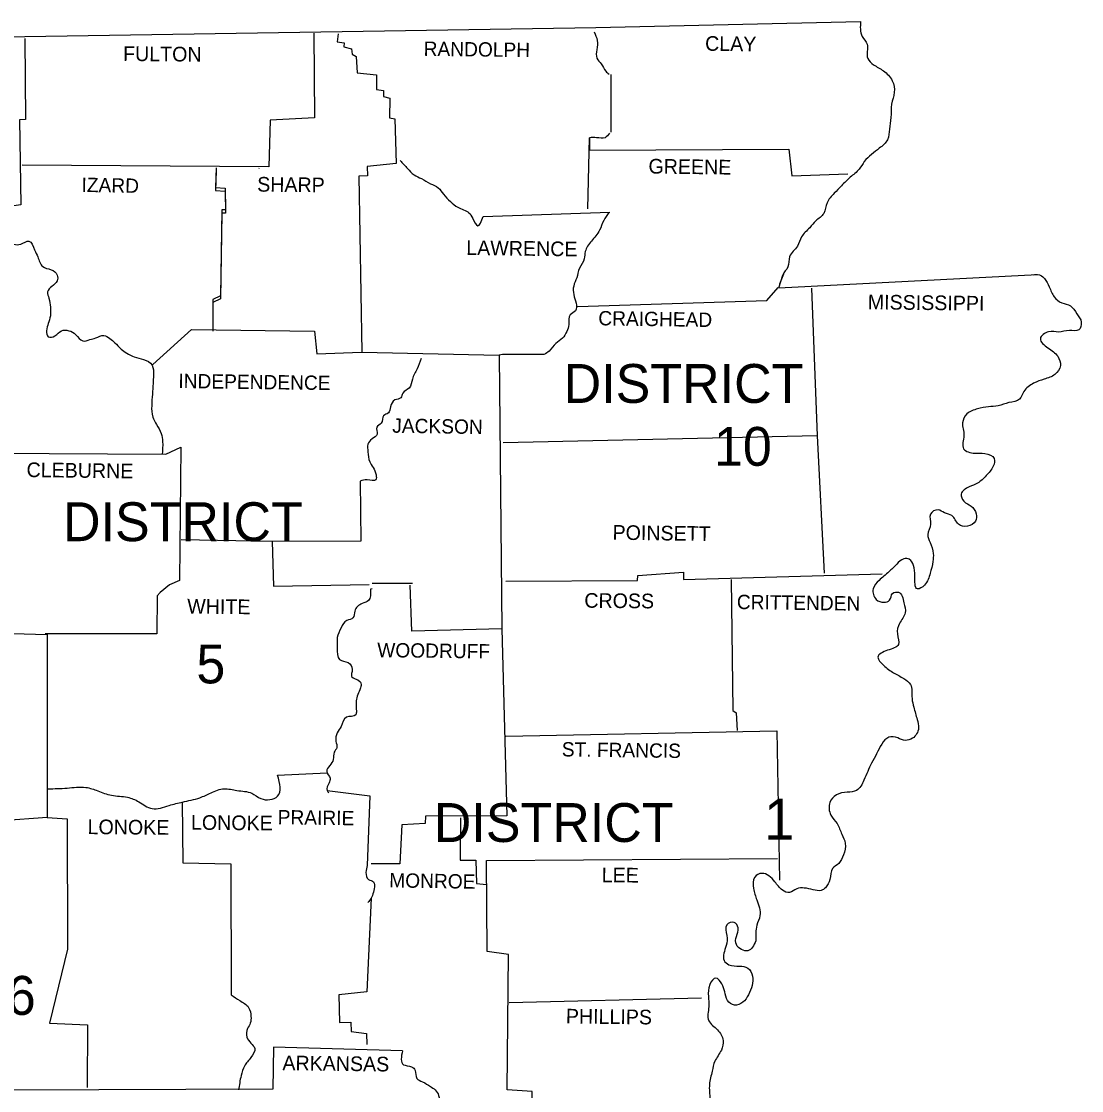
# Model space of a CAD drawing. Extents: x -17668 to 16999, y -17303 to 5867.
# Drawn here: x -16002 to -14292, y 4141 to 5867 of the extents above; entities that cross this region are included whole.
import ezdxf

# ---------------------------------------------------------------- set-up
doc = ezdxf.new("R2010")
doc.units = 0
for name, color, linetype in [('1', 7, 'Continuous'), ('2', 7, 'Continuous'), ('3', 7, 'Continuous')]:
    doc.layers.add(name, color=color, linetype=linetype)

msp = doc.modelspace()

# ---------------------------------------------------------------- linework, layer by layer
at = {"layer": '1'}
for p, q in [((-14780.6, 5436.9), (-14774, 5457.3)), ((-14779, 5443.5), (-14772.4, 5459.5)), ((-15436.7, 4960.3), (-15371.2, 4960.3))]:
    msp.add_line(p, q, dxfattribs=at)
for points in [[(-17667.8, 5841.4), (-16777.9, 5840.9), (-15996.9, 5842.5), (-15075.6, 5856.8), (-14648.6, 5866.7)], [(-15996.9, 5839.2), (-15995.8, 5708.2), (-16005.2, 5707.7), (-16003.5, 5570.7), (-16042.1, 5565.2), (-16038.8, 5528.3), (-16025.5, 5511.2), (-16026.6, 5467.7), (-16101.5, 5465), (-16104.2, 5397.8), (-16172.5, 5395.6), (-16175.8, 5314.2), (-16171.9, 5307.6), (-16170.3, 5177.7), (-16052.5, 5170), (-16054.2, 4880), (-15960.6, 4877.2), (-15960.6, 4582.2), (-16034.4, 4576.7), (-16039.9, 4511.8), (-16163.7, 4511.2)], [(-15530.8, 5847.5), (-15529.7, 5711), (-15601.2, 5707.1), (-15603.4, 5632.3), (-16001.3, 5634.5)], [(-15491.2, 5846.9), (-15492.8, 5833.7), (-15481.8, 5832.1), (-15482.3, 5825.5), (-15469.7, 5822.7), (-15468.6, 5813.9), (-15462.5, 5810.1), (-15460.9, 5783.6), (-15429.5, 5780.3), (-15429.5, 5756.7), (-15418, 5755), (-15418, 5745.7), (-15408, 5742.9), (-15408.6, 5711), (-15399.8, 5709.3), (-15397.6, 5637.2), (-15444.4, 5632.8), (-15443.8, 5617.4), (-15458.1, 5616.9), (-15453.2, 5332.9), (-15231.4, 5327.9), (-15227.5, 4886.6), (-15372.3, 4882.7), (-15375, 4957)], [(-15051.4, 5780.9), (-15051.4, 5687.9)], [(-15088.8, 5564.1), (-15086.1, 5679.1), (-15086.1, 5658.7), (-14764.1, 5660.4), (-14759.7, 5617.4), (-14668.9, 5620.7)], [(-15688.2, 5630.6), (-15689.3, 5598.7), (-15673.9, 5597.6), (-15673.3, 5562.4), (-15678.8, 5562.4), (-15681, 5423.7), (-15693.7, 5418.2), (-15693.7, 5372)], [(-15688.2, 5625.7), (-15689.3, 5593.8), (-15673.9, 5592.7), (-15673.3, 5557.4), (-15678.8, 5557.4), (-15681, 5418.8), (-15693.7, 5413.3), (-15693.7, 5367)], [(-15619.4, 5629.5), (-15618.8, 5630.1)], [(-15257.3, 5551.9), (-15053.1, 5559.1)], [(-14780.6, 5436.9), (-14362.9, 5458.4)], [(-15105.4, 5406.7), (-14799.9, 5416.6), (-14781.7, 5437.5)], [(-14727.8, 5436.4), (-14718.5, 5198.1), (-14707.4, 4976.3)], [(-15790.5, 5313.1), (-15727.8, 5369.8), (-15529.7, 5367), (-15525.8, 5330.2), (-15453.7, 5332.9)], [(-15159.3, 5329.1), (-15226.4, 5329.1), (-15231.4, 5327.9)], [(-14718.5, 5198.1), (-15225.3, 5186.5)], [(-16052.5, 5170), (-15769.6, 5168.3), (-15745.4, 5179.9), (-15747.1, 4964.7), (-15763.6, 4957.6), (-15778.4, 4944.9), (-15783.4, 4940), (-15783.9, 4878.3), (-15963.9, 4878.3)], [(-15455.9, 5124.9), (-15454.8, 5028), (-15597.9, 5027.5), (-15744.9, 5030.2)], [(-15597.9, 5027.5), (-15595.7, 4955.4), (-15441.1, 4958.1)], [(-15220.9, 4963.6), (-15008.5, 4964.7), (-15007.9, 4972.4), (-14934.2, 4977.9), (-14934.2, 4966.4), (-14613.9, 4975.2)], [(-14857.1, 4966.4), (-14854.4, 4754.5), (-14849.4, 4751.2), (-14847.8, 4722.6)], [(-15436.7, 4951), (-15439.4, 4950.4)], [(-15227.5, 4886.6), (-15219.3, 4585), (-15350.3, 4584.4), (-15350.8, 4572.3), (-15388.8, 4570.1), (-15392.1, 4507.4), (-15438.3, 4507.4)], [(-15220.9, 4713.2), (-14783.9, 4722)], [(-14783.9, 4722), (-14779.5, 4481)], [(-15589.1, 4650.5), (-15509.3, 4654.3)], [(-15509.3, 4625.7), (-15440.5, 4616.9), (-15444.4, 4504.6)], [(-15743.2, 4607.5), (-15742.1, 4509), (-15664.5, 4507.4), (-15664, 4296)], [(-15960.6, 4582.2), (-15928.7, 4580), (-15928.1, 4369.8), (-15956.8, 4250.4), (-15895.7, 4247.6), (-15896.2, 4146.3)], [(-15294.1, 4581.7), (-15294.7, 4513.4), (-15269.4, 4513.4), (-15268.3, 4475.5), (-15252.3, 4473.8)], [(-15220.9, 4025.3), (-15178, 4028), (-15178.6, 4139.7), (-15218.7, 4142.5), (-15216.5, 4361), (-15251.2, 4365.9), (-15252.3, 4512.9), (-14782.8, 4516.2)], [(-15438.3, 4451.8), (-15444.9, 4301), (-15490.1, 4296), (-15489, 4251.5), (-15470.8, 4252), (-15470.2, 4236.6), (-15445.5, 4233.8), (-15444.9, 4215.7)], [(-15215.4, 4283.4), (-14905, 4291.1)], [(-15387.7, 4205.8), (-15595.7, 4211.3), (-15596.8, 4143.6), (-16017.8, 4141.9)]]:
    msp.add_lwpolyline(points, dxfattribs=at)
for points in [[(-14648.6, 5866.7), (-14645.8, 5842.5), (-14638.1, 5829.9), (-14637, 5806.8), (-14627.6, 5796.9), (-14611.7, 5786.9), (-14597.4, 5771), (-14594.1, 5752.3), (-14598.5, 5733), (-14599.6, 5711.5), (-14601.8, 5692.8), (-14605.1, 5675.8), (-14618.3, 5662), (-14630.9, 5652.1), (-14642.5, 5640.6), (-14650.8, 5628.4), (-14665.1, 5615.2), (-14679.4, 5601.5), (-14690.9, 5589.4), (-14702.5, 5574), (-14708, 5556.9), (-14720.7, 5544.8), (-14730.6, 5533.8), (-14743.8, 5518.9), (-14750.4, 5504.1), (-14763, 5487), (-14765.8, 5470.5), (-14774, 5457.3), (-14774.6, 5455.1)], [(-15078.4, 5849.7), (-15073.4, 5835.9), (-15074, 5821.1), (-15074, 5807.3), (-15066.8, 5798), (-15059.7, 5786.4), (-15054.2, 5781.4)], [(-15053.6, 5686.2), (-15060.8, 5679.1), (-15074.5, 5679.1), (-15086.1, 5679.1)], [(-15391.5, 5642.2), (-15379.4, 5629.5), (-15369, 5619.1), (-15356.9, 5613), (-15342.6, 5604.8), (-15329.9, 5598.2), (-15321.6, 5587.7), (-15310.1, 5576.2), (-15298.5, 5566.8), (-15280.4, 5558), (-15274.3, 5548.6), (-15266.1, 5537.1), (-15257.3, 5551.9)], [(-15054.7, 5558.5), (-15063, 5545.3), (-15069.6, 5529.9), (-15082.8, 5512.3), (-15092.7, 5495.3), (-15094.3, 5483.7), (-15102.1, 5468.3), (-15106.5, 5452.9), (-15111.4, 5439.7), (-15111.4, 5425.9), (-15107.6, 5412.2), (-15108.7, 5399.5), (-15116.9, 5393.4), (-15119.1, 5377.5), (-15122.4, 5366.5), (-15129.6, 5355.5), (-15140, 5347.2), (-15151, 5334.6), (-15159.3, 5329.1)], [(-16025.5, 5511.2), (-16003.5, 5507.4), (-15990.3, 5512.3), (-15981, 5498), (-15976, 5487), (-15967.8, 5471), (-15954.6, 5466.1), (-15944.6, 5457.3), (-15944.6, 5447.9), (-15953.4, 5439.1), (-15960.1, 5430.3), (-15957.9, 5419.9), (-15955.7, 5405.5), (-15955.7, 5391.8), (-15959, 5379.1), (-15961.7, 5367.6), (-15959, 5357.7), (-15948.5, 5359.3), (-15937.5, 5367.6), (-15925.9, 5367.6), (-15914.9, 5361.5), (-15903.4, 5351.1), (-15891.8, 5353.3), (-15882.5, 5356), (-15869.2, 5359.9), (-15859.9, 5354.9), (-15851.6, 5348.3), (-15841.7, 5337.9), (-15832.4, 5331.3), (-15820.3, 5325.2), (-15805.4, 5321.3), (-15791.6, 5312), (-15789.4, 5296), (-15790, 5282.3), (-15791.1, 5265.2), (-15792.2, 5246.5), (-15790.5, 5228.3), (-15784.5, 5216.2), (-15776.8, 5201.9), (-15774.6, 5188.7), (-15775.1, 5167.8)], [(-14369, 5457.8), (-14362.9, 5458.4), (-14344.2, 5438.6), (-14336, 5422.1), (-14323.9, 5412.7), (-14310.1, 5407.8), (-14299.6, 5395.1), (-14292.5, 5381.3), (-14296.3, 5369.2), (-14311.7, 5368.1), (-14328.8, 5365.4), (-14345.3, 5365.9), (-14358.5, 5354.9), (-14346.4, 5340.1), (-14330.5, 5326.3), (-14326.1, 5311.4), (-14334.9, 5297.1), (-14352.5, 5289.4), (-14369.5, 5282.8), (-14384.9, 5269.6), (-14392.1, 5257), (-14409.2, 5251.5), (-14426.8, 5246.5), (-14442.2, 5244.8), (-14459.8, 5241.5), (-14476.9, 5233.3), (-14484, 5219), (-14481.8, 5198.6), (-14482.4, 5177.2), (-14464.2, 5170), (-14448.2, 5169.4), (-14432.8, 5161.2), (-14434.5, 5149.1), (-14446, 5133.7), (-14459.8, 5121.6), (-14473.5, 5115.5), (-14486.2, 5104), (-14481.8, 5092.4), (-14470.2, 5084.7), (-14462, 5072), (-14463.1, 5060.5), (-14476.3, 5052.2), (-14490.6, 5055.5), (-14501.1, 5069.3), (-14513.2, 5073.7), (-14523.6, 5078.6), (-14535.7, 5071.5), (-14535.7, 5055.5), (-14540.1, 5038.5), (-14536.3, 5025.8), (-14531.3, 5008.2), (-14531.9, 4995), (-14536.3, 4976.3), (-14545.6, 4957), (-14556.7, 4951), (-14561.1, 4971.9), (-14563.3, 4988.9), (-14569.9, 4998.8), (-14578.7, 4999.4), (-14590.2, 4991.1), (-14602.9, 4978.5), (-14618.8, 4964.7), (-14628.2, 4951), (-14623.2, 4933.9), (-14611.1, 4929.5), (-14601.8, 4932.8), (-14596.8, 4943.8), (-14587.5, 4945.5), (-14578.7, 4928.4)], [(-15357.4, 5323), (-15364, 5305.9), (-15371.7, 5289.4), (-15376.7, 5275.1), (-15387.1, 5266.9), (-15390.4, 5259.2), (-15399.8, 5255.9), (-15406.9, 5244.8), (-15410.3, 5234.9), (-15418, 5230.5), (-15421.8, 5218.4), (-15429, 5211.8), (-15428.4, 5200.8), (-15436.7, 5193.1), (-15443.3, 5184.3), (-15443.3, 5172.2), (-15440.5, 5156.2), (-15435, 5146.9), (-15430.1, 5134.8), (-15430.6, 5127.1), (-15444.4, 5127.1), (-15455.9, 5124.9)], [(-15439.4, 4950.4), (-15442.2, 4932.2), (-15452.6, 4927.3), (-15464.7, 4915.2), (-15467.5, 4904.2), (-15477.4, 4899.8), (-15486.7, 4888.2), (-15492.8, 4872.3), (-15492.8, 4855.7), (-15489, 4837), (-15475.2, 4832.1), (-15468.6, 4821.1), (-15469.7, 4809.5), (-15456.5, 4801.8), (-15454.3, 4795.2), (-15456.5, 4788.1), (-15462.5, 4767.7), (-15462, 4753.9), (-15463.1, 4747.9), (-15477.9, 4744), (-15486.7, 4729.2), (-15492.8, 4718.7), (-15495, 4704.9), (-15493.4, 4695), (-15497.8, 4687.3), (-15499.4, 4675.8), (-15504.9, 4665.9), (-15509.9, 4656.5), (-15504.4, 4645.5), (-15506, 4637.8), (-15509.3, 4625.7), (-15506.6, 4621.8)], [(-14578.7, 4928.4), (-14576.5, 4912.4), (-14585.8, 4895.4), (-14589.1, 4878.3), (-14587.5, 4861.2), (-14605.1, 4851.9), (-14620.5, 4840.9), (-14611.7, 4827.7), (-14595.2, 4815.6), (-14578.7, 4806.2), (-14568.2, 4796.9), (-14565.5, 4774.3), (-14562.7, 4760), (-14557.2, 4740.2), (-14555, 4726.4), (-14564.9, 4709.9), (-14576.5, 4706.6), (-14588.6, 4710.5), (-14602.9, 4711.6), (-14614.4, 4700.5), (-14622.7, 4685.1), (-14630.9, 4669.7), (-14637, 4656.5), (-14643.1, 4642.2), (-14655.2, 4625.7), (-14670, 4622.9), (-14687.6, 4618.5), (-14698.1, 4606.4), (-14696.4, 4586.1), (-14686.5, 4572.3), (-14678.8, 4555.3), (-14673.3, 4540.4), (-14676.1, 4521.7), (-14683.8, 4507.9), (-14693.7, 4499.7), (-14698.1, 4482.1), (-14705.2, 4468.8), (-14711.9, 4464.4), (-14725.1, 4465.5), (-14739.4, 4468.3), (-14751.5, 4467.2), (-14763, 4461.1), (-14774.6, 4465), (-14786.7, 4478.2), (-14796.6, 4488.1), (-14807.6, 4492), (-14819.2, 4485.9), (-14821.4, 4467.7), (-14815.9, 4449), (-14810.9, 4423.7), (-14815.9, 4408.3), (-14817.5, 4383)], [(-15959.5, 4628.5), (-15928.7, 4629.6), (-15898.4, 4630.7), (-15879.2, 4625.1), (-15857.1, 4618), (-15831.3, 4614.7), (-15813.1, 4607.5), (-15791.6, 4596.5), (-15764.1, 4601.5), (-15742.7, 4607), (-15714.6, 4614.1), (-15696.4, 4621.8), (-15675.5, 4628.5), (-15654.6, 4625.7), (-15630.9, 4621.3), (-15616.1, 4612.5), (-15589.1, 4616.3), (-15589.1, 4650.5)], [(-15444.4, 4504.6), (-15446.6, 4493.6), (-15442.2, 4482.1), (-15434.5, 4478.2), (-15433.4, 4467.2), (-15436.1, 4456.2), (-15438.3, 4451.8), (-15443.3, 4445.2)], [(-14817.5, 4383), (-14830.2, 4367), (-14848.9, 4376.9), (-14848.9, 4390.1), (-14846.1, 4403.9), (-14852.7, 4412.7), (-14864.3, 4408.9), (-14864.3, 4391.8), (-14865.4, 4375.3), (-14868.7, 4351.6), (-14861, 4344.5), (-14843.4, 4342.3), (-14830.7, 4339), (-14823, 4326.3), (-14823.6, 4310.9), (-14829.6, 4296), (-14838.4, 4283.9), (-14852.2, 4279.5), (-14863.2, 4286.7), (-14867.6, 4301), (-14872.6, 4313.6), (-14881.9, 4323), (-14891.8, 4312.5), (-14894, 4293.3), (-14893.5, 4276.8), (-14893.5, 4254.2), (-14879.2, 4239.3), (-14870.4, 4222.3), (-14873.1, 4206.9), (-14883.6, 4188.7), (-14888, 4172.8), (-14892.4, 4151.3), (-14891.8, 4127.6), (-14895.7, 4104.5), (-14903.4, 4089.1), (-14917.7, 4076.4), (-14927, 4068.2), (-14934.7, 4059.9), (-14938.6, 4043.4), (-14941.3, 4031.9), (-14951.8, 4018.1), (-14960.1, 4017), (-14966.7, 4022.5), (-14968.9, 4031.9), (-14968.9, 4041.2), (-14973.3, 4050.6), (-14987, 4054.4), (-14998, 4053.9), (-15003, 4046.2), (-14995.8, 4024.7), (-14993.1, 4011), (-14996.9, 3992.2), (-14994.7, 3990), (-15014.5, 3979.6), (-15030.5, 3977.9), (-15043.7, 3974.1), (-15056.4, 3965.8), (-15062.4, 3953.7), (-15071.2, 3943.8), (-15078.9, 3934.5), (-15089.4, 3930.1), (-15101, 3932.3), (-15116.4, 3933.9), (-15125.2, 3922.9), (-15122.4, 3906.9), (-15112, 3897.6), (-15096.5, 3893.2), (-15080.6, 3894.3), (-15065.2, 3895.9), (-15050.9, 3888.2), (-15053.6, 3873.4), (-15067.4, 3866.2), (-15087.7, 3864), (-15104.3, 3865.7), (-15124.1, 3861.3), (-15134, 3848.6), (-15128.5, 3829.3), (-15107, 3821.6), (-15097.1, 3803.5), (-15096.5, 3786.4), (-15103.7, 3763.8), (-15113.6, 3753.4), (-15132.9, 3749), (-15147.7, 3746.2), (-15149.9, 3720.9), (-15156.5, 3708.3), (-15168.1, 3704.4), (-15184.6, 3712.7), (-15194.5, 3716.5), (-15206.6, 3722), (-15222, 3731.4), (-15233.6, 3729.7), (-15230.3, 3705.5), (-15229.2, 3704.4), (-15216, 3686.2), (-15202.8, 3671.9), (-15196.7, 3654.9)], [(-15664, 4296), (-15650.2, 4286.7), (-15635.9, 4275.7), (-15632, 4260.8), (-15633.1, 4250.4), (-15637.5, 4241.6), (-15638.6, 4227.8), (-15632, 4217.9), (-15626, 4209.6), (-15632, 4194.8), (-15642.5, 4181), (-15648, 4165.6), (-15651.9, 4142.5)], [(-15387.7, 4205.8), (-15386, 4183.2), (-15372.8, 4179.9), (-15367.3, 4173.9), (-15364.6, 4161.2), (-15355.2, 4155.7), (-15342.6, 4148), (-15334.9, 4142.5), (-15329.3, 4133.7), (-15326, 4119.4), (-15317.2, 4110), (-15305.1, 4105.6), (-15296.3, 4095.2), (-15290.8, 4080.3), (-15282, 4073.7), (-15273.2, 4062.1), (-15268.8, 4057.2), (-15261.1, 4044), (-15253.4, 4037.4), (-15247.9, 4033.5), (-15239.1, 4030.8), (-15228.1, 4023.6), (-15220.9, 4012.6), (-15220.9, 4004.3), (-15223.7, 3991.7), (-15225.9, 3978.5), (-15227, 3963.6), (-15228.1, 3950.4), (-15223.1, 3939.4), (-15225.9, 3922.9), (-15231.4, 3914.1), (-15231.9, 3902), (-15233.6, 3883.8), (-15235.8, 3873.4), (-15240.7, 3856.3), (-15247.9, 3847.5)]]:
    msp.add_spline(points, degree=3, dxfattribs=at)

# ---------------------------------------------------------------- texts
msp.add_text('1', height=66, dxfattribs=at).set_placement((-14804.3, 4546.4))
at = {"layer": '2'}
for s, height, rotation, p in [('RANDOLPH', 23.11, 359.2583, (-15353.6, 5811.2)), ('CLAY', 23.66, 359.2258, (-14899.5, 5819.4)), ('FULTON', 23.66, 359.4996, (-15838.4, 5802.9)), ('GREENE', 23.67, 359.2361, (-14990.9, 5621.3)), ('IZARD', 23.11, 358.9258, (-15905.6, 5591.6)), ('SHARP', 23.66, 359.3905, (-15622.1, 5592.1)), ('LAWRENCE', 23.67, 359.2678, (-15284.8, 5489.8)), ('MISSISSIPPI', 23.66, 359.3097, (-14637, 5402.2)), ('CRAIGHEAD', 23.11, 359.1159, (-15071.8, 5376.4)), ('INDEPENDENCE', 23.108, 359.2187, (-15749.3, 5275.1)), ('JACKSON', 23.11, 359.1352, (-15404.2, 5203)), ('CLEBURNE', 23.66, 359.2535, (-15994.2, 5131.5)), ('POINSETT', 23.66, 359.1987, (-15048.8, 5030.4)), ('WHITE', 23.67, 359.3139, (-15735, 4911.3)), ('CROSS', 23.66, 359.3839, (-15094.3, 4920.7)), ('CRITTENDEN', 23.11, 359.213, (-14848.3, 4918.5)), ('WOODRUFF', 23.11, 359.2748, (-15428.4, 4840.9)), ('ST. FRANCIS', 23.108, 359.2216, (-15130.7, 4680.7)), ('PRAIRIE', 23.11, 359.2116, (-15589.1, 4571.2)), ('LONOKE', 23.67, 359.4974, (-15895.7, 4555.3)), ('LONOKE', 23.67, 359.4974, (-15728.9, 4562.4)), ('MONROE', 23.11, 359.0331, (-15409.1, 4469.4)), ('LEE', 23.67, 359.4327, (-15066.3, 4477.7)), ('PHILLIPS', 23.66, 359.3179, (-15124.1, 4249.8)), ('ARKANSAS', 23.66, 359.2678, (-15581.4, 4174.4))]:
    msp.add_text(s, height=height, rotation=rotation, dxfattribs=at).set_placement(p)
at = {"layer": '3'}
for s, height, p in [('DISTRICT', 62.74, (-15127.6, 5251.1)), ('10', 62.74, (-14885.1, 5149.6)), ('DISTRICT', 62.74, (-15935.3, 5028)), ('5', 62.7, (-15720.1, 4798.5)), ('DISTRICT', 62.74, (-15337.1, 4542.6)), ('DISTRICT 6', 62.74, (-16436.1, 4263.6))]:
    msp.add_text(s, height=height, dxfattribs=at).set_placement(p)

doc.saveas('drawing.dxf')
